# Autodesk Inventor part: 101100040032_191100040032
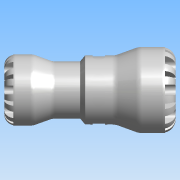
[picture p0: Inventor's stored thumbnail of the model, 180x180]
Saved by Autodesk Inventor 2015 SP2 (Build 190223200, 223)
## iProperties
Created: 2016-12
Part Number: 101100040032_191100040032
Material: PVC-Piping
Description: PLASSON REDUCING COUPLING 40X32 SERIES 1
Document SubType Name: Modeling
Designer: KIM
Mass: 113.204 g
Surface Area: 237.851 cm^2
Volume: 80.8599 cm^3
Density: 1.4 g/cm^3
Appearance: Smooth - White
Author: KIM
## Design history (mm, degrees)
derived "1011.ipt"
feature "Solid1::1011.ipt"
tag "TaggingFeature1"
body "Solid1"
other parameters: "d0" = 139, "d2" = 29.82, "d5" = 48, "d6" = 71, "d7" = 3.33333, "d8" = 58, "d9" = 32, "d11" = 23.1, "d12" = 55, "d13" = 2.66667, "d14" = 56, "d15" = 46.4, "d16" = 20 deg, "d17" = 20 deg, "d18" = 130 deg, "d22" = 8.8, "d25" = 8.8, "d26" = 0, "d28" = 360 deg, "d30" = 8 deg, "d31" = 0.8, "d32" = 8 deg, "d33" = 0.8, "d35" = 0, "d37" = 360 deg, "d39" = 7.2, "d42" = 7.2, "d43" = 0, "d45" = 360 deg, "d47" = 0.64, "d48" = 8 deg, "d49" = 8 deg, "d50" = 0.64, "d52" = 0, "d54" = 360 deg, "d56" = 11.6, "d57" = 14, "d58" = 0.5, "d60" = 8.4, "d62" = 14.4, "d63" = 0, "d66" = 0, "d68" = 360 deg, "d75" = 10.85912, "d77" = 54.6, "d78" = 0.7, "d1" = 32, "H_" = 139, "l_" = 71, "E1" = 58, "l1" = 55, "Plasson" = 1, "d20" = 9, "d21" = 11, "d24" = 48, "d40" = 58, "d59" = 21.71825
